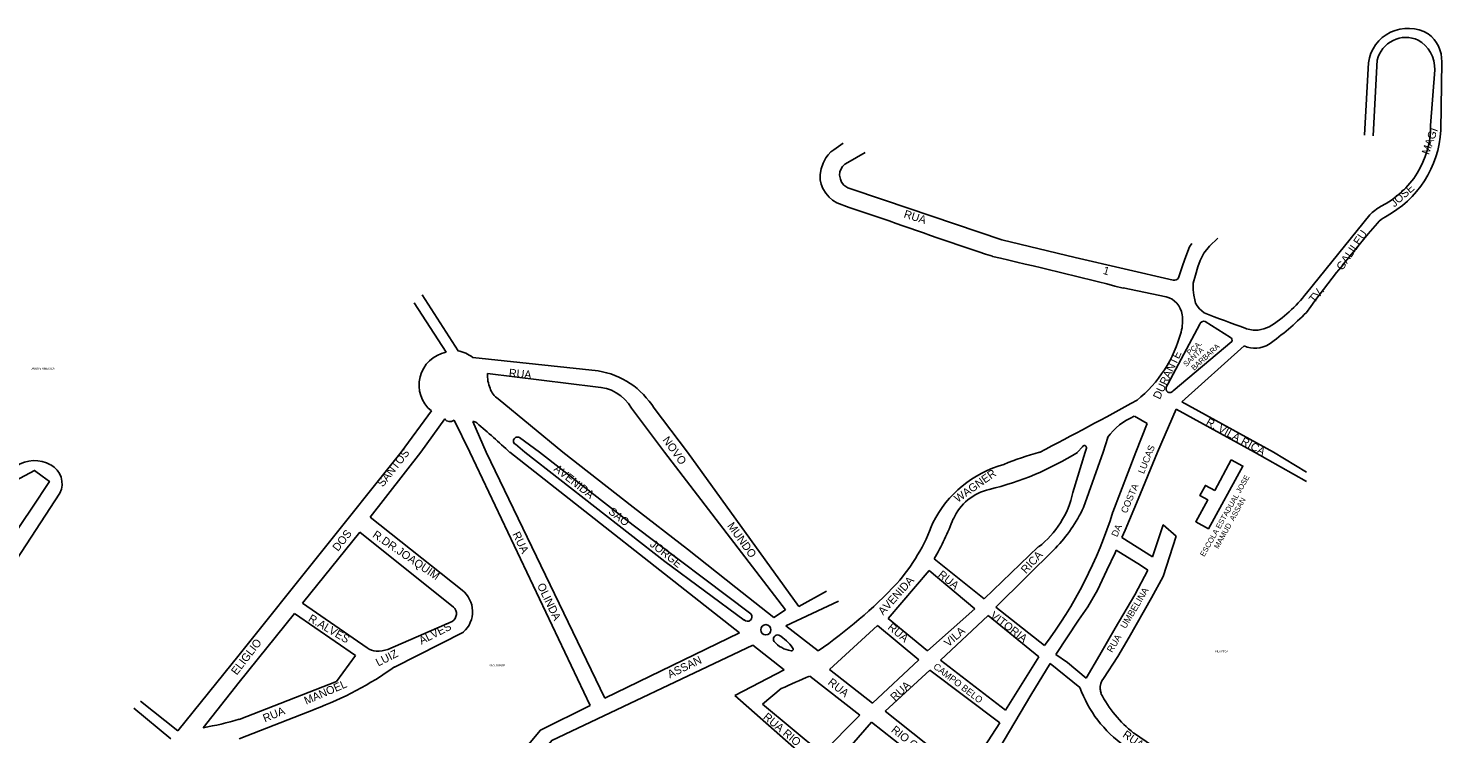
# Model space of a CAD drawing. Extents: x 325709 to 364434, y 7573432 to 7597073.
# Drawn here: x 335123 to 336183, y 7590791 to 7591320 of the extents above; entities that cross this region are included whole.
import ezdxf

# ---------------------------------------------------------------- set-up
doc = ezdxf.new("R2010")
doc.units = 0
for name, color, linetype in [('EDIFEXISTENT', 7, 'Continuous'), ('EDIFIDENTIF', 7, 'Continuous'), ('EDIFOBRAEXIS', 7, 'Continuous'), ('LIMITE_BAIRROS_MUNICIPIOS', 7, 'Continuous'), ('LOGRADOURO', 7, 'Continuous'), ('LOGRADOURO_TEXTO', 7, 'Continuous')]:
    doc.layers.add(name, color=color, linetype=linetype)

msp = doc.modelspace()

# ---------------------------------------------------------------- linework, layer by layer
at = {"layer": 'EDIFEXISTENT'}
msp.add_line((336012.7, 7590973.3), (336025, 7590996.4), dxfattribs=at)
msp.add_lwpolyline([(336025, 7590996.4), (336033.8, 7590991.6), (336007.9, 7590944.6), (335998.4, 7590949.9), (336007.4, 7590966.3), (336001.5, 7590969.5), (336005.7, 7590977.1), (336012.7, 7590973.3)], dxfattribs=at)
at = {"layer": 'EDIFOBRAEXIS'}
for p, q in [((335491.4, 7591012.9), (335506.4, 7591001.9)), ((335495.4, 7591001.9), (335488.4, 7591007.9))]:
    msp.add_line(p, q, dxfattribs=at)
for points in [[(335659.9, 7590876.3), (335600.5, 7590920.1), (335495.4, 7591001.9)], [(335506.4, 7591001.9), (335576.7, 7590947.3), (335664.9, 7590880.9)]]:
    msp.add_lwpolyline(points, dxfattribs=at)
msp.add_circle((335676.1, 7590869), 3.83, dxfattribs=at)
for centre, radius, start, end in [((335489.9, 7591010.4), 2.92, 59.0362, 239.0362), ((335662.3, 7590878.7), 3.39, 224.4723, 39.9732), ((335684.9, 7590862), 3.1, 73.1087, 215.8277), ((335670.3, 7590837.8), 31.3, 34.1923, 60.3582), ((335698.2, 7590874.1), 21.1, 221.1894, 261.4386), ((335695.4, 7590854.4), 1.23, 255.2992, 51.7204)]:
    msp.add_arc(centre, radius, start, end, dxfattribs=at)
at = {"layer": 'LOGRADOURO'}
for p, q in [((336127.8, 7591293.8), (336124.9, 7591239.5)), ((336134.5, 7591295.8), (336131.5, 7591238.9)), ((336174.4, 7591246.6), (336177.6, 7591288.4)), ((336182.2, 7591243.1), (336182.8, 7591294.3)), ((336081.4, 7591121.2), (336128.8, 7591179.9)), ((335418.4, 7591119.9), (335445.4, 7591077.9)), ((335944, 7591125), (335976.2, 7591118.3)), ((335412.4, 7591113.9), (335436.4, 7591076.9)), ((335977.4, 7591052.9), (336001.4, 7591097.9)), ((335988.1, 7591105), (335988.1, 7591105)), ((336005.4, 7591099.9), (336024.4, 7591087.9)), ((336025.4, 7591084.9), (335981.4, 7591047.9)), ((335987.9, 7591039.6), (336034.7, 7591081.6)), ((335456.4, 7591072.9), (335550.4, 7591062.9)), ((335467.4, 7591060.9), (335548.4, 7591050.9)), ((335425.4, 7591032.9), (335402.8, 7591001.9)), ((335524, 7591001.9), (335475.4, 7591041.9)), ((335575.4, 7591034.9), (335600.2, 7591001.9)), ((335592.4, 7591034.9), (335617.4, 7591001.9)), ((335969.7, 7591001.9), (335983.8, 7591034.2)), ((335983.8, 7591034.2), (336042.4, 7591001.9)), ((336056.6, 7591001.9), (335987.9, 7591039.6)), ((335417.4, 7591001.9), (335435.4, 7591026.9)), ((335442.4, 7591025.9), (335454.2, 7591001.9)), ((335466.5, 7591001.9), (335456.4, 7591024.9)), ((335952.4, 7591028.9), (335962, 7591023.4)), ((335962, 7591023.4), (335953.4, 7591001.9)), ((335928.9, 7591001.9), (335932.4, 7591012.9)), ((335281.4, 7590850.1), (335402.8, 7591001.9)), ((335379.6, 7590953.3), (335417.4, 7591001.9)), ((335454.2, 7591001.9), (335544.5, 7590812.2)), ((335555.4, 7590817.8), (335466.5, 7591001.9)), ((335484.2, 7591001.9), (335656.5, 7590866.7)), ((335600.2, 7591001.9), (335690.8, 7590884)), ((335700.8, 7590886.5), (335617.4, 7591001.9)), ((335915.6, 7591001.9), (335906.2, 7590971.9)), ((335909.8, 7591001.9), (335913.4, 7591005.9)), ((335914.2, 7590960.6), (335928.9, 7591001.9)), ((335916.4, 7591004.9), (335915.6, 7591001.9)), ((335953.4, 7591001.9), (335936.3, 7590957.2)), ((336042.4, 7591001.9), (336081.4, 7590980)), ((336056.6, 7591001.9), (336081.4, 7590987.1)), ((335843.6, 7590974.2), (335843.6, 7590974.2)), ((335448.5, 7590898.6), (335379.6, 7590953.3)), ((335328.8, 7590888.8), (335371.7, 7590942.2)), ((335371.7, 7590942.2), (335441.9, 7590886)), ((335966, 7590923.7), (335942.9, 7590938)), ((335880.4, 7590931.1), (335839.9, 7590892.1)), ((335848.6, 7590886), (335893.3, 7590930.1)), ((335839.9, 7590892.1), (335802.3, 7590922)), ((335767.8, 7590877.4), (335798.6, 7590913.5)), ((335798.6, 7590913.5), (335832.9, 7590884.6)), ((335721.7, 7590897.9), (335700.8, 7590886.5)), ((335377.2, 7590855.5), (335328.8, 7590888.8)), ((335730.5, 7590890.4), (335691.2, 7590871.9)), ((335832.9, 7590884.6), (335797.2, 7590853.2)), ((335885.1, 7590857.2), (335848.6, 7590886)), ((335322.9, 7590881.2), (335281.4, 7590829.7)), ((335368.6, 7590849.6), (335322.9, 7590881.2)), ((335441, 7590875.3), (335392.7, 7590854.3)), ((335690.8, 7590884), (335682.2, 7590878.2)), ((335797.2, 7590853.2), (335767.8, 7590877.4)), ((335807, 7590846.2), (335842.9, 7590879.6)), ((335842.9, 7590879.6), (335880.8, 7590848.8)), ((335397.9, 7590841.1), (335449.4, 7590867.3)), ((335656.5, 7590866.7), (335555.4, 7590817.8)), ((335691.2, 7590871.9), (335715.4, 7590853.1)), ((335723.9, 7590839.3), (335759.9, 7590872.2)), ((335759.9, 7590872.2), (335790.8, 7590846.5)), ((335666.3, 7590857.5), (335690, 7590839.1)), ((335235.4, 7590793.4), (335281.4, 7590850.1)), ((335790.8, 7590846.5), (335756, 7590813.9)), ((335855.9, 7590808.8), (335807, 7590846.2)), ((335880.8, 7590848.8), (335855.9, 7590808.8)), ((335889.2, 7590843.6), (335911.4, 7590825.8)), ((335690, 7590839.1), (335652.9, 7590819.7)), ((335709, 7590834.3), (335746.6, 7590804.9)), ((335756, 7590813.9), (335723.9, 7590839.3)), ((335765.7, 7590807.9), (335799.1, 7590838.8)), ((335799.1, 7590838.8), (335851.5, 7590799.3)), ((335281.4, 7590829.7), (335254.3, 7590795.6)), ((335673.7, 7590813.2), (335687.7, 7590824.9)), ((335230.1, 7590787.2), (335202.4, 7590810.3)), ((335207.4, 7590815.5), (335235.4, 7590793.4)), ((335652.9, 7590819.7), (335701.3, 7590777)), ((335718, 7590776.2), (335673.7, 7590813.2)), ((335281.4, 7590787.2), (335338.2, 7590809.6)), ((335746.6, 7590804.9), (335718, 7590776.2)), ((335723, 7590762.7), (335755.4, 7590799.7)), ((335755.4, 7590799.7), (335820.2, 7590748.9)), ((335826.1, 7590760.2), (335765.7, 7590807.9)), ((335851.5, 7590799.3), (335826.1, 7590760.2))]:
    msp.add_line(p, q, dxfattribs=at)
for points in [[(335734.1, 7591233.5), (335727.2, 7591228.6), (335724.8, 7591226.9), (335722.8, 7591224.8), (335721.1, 7591222.5), (335719.1, 7591218.6), (335717.5, 7591214.3), (335716.8, 7591210.1), (335716.9, 7591206.1), (335717.5, 7591202.8), (335718.8, 7591199.5), (335721, 7591196), (335723.5, 7591193), (335726.1, 7591190.7), (335729.4, 7591188.8), (335738.6, 7591185.3), (335763.4, 7591177)], [(335984.1, 7591131.3), (335983.6, 7591131), (335982.7, 7591130.8), (335981.5, 7591130.9), (335908.1, 7591147.9), (335853.1, 7591161.1), (335765.2, 7591190.8), (335737.5, 7591200.1), (335734.7, 7591202.1), (335732.9, 7591204.2), (335732, 7591206.6), (335731.4, 7591209.5), (335731.5, 7591212), (335732.5, 7591214.2), (335733.5, 7591216), (335735.4, 7591217.8), (335737.5, 7591219.1), (335750.6, 7591226.6)], [(336014.9, 7591162.4), (336008.7, 7591156.4), (336004.4, 7591151.2), (336001.7, 7591145.6), (335999.9, 7591140.8), (335998.1, 7591134.5), (335996.4, 7591128.7), (335996.4, 7591123.7), (335997, 7591119.6), (335997.7, 7591116.1), (335998.3, 7591113.6), (335999.4, 7591111.6), (336001.3, 7591109.5), (336004.6, 7591106.3)], [(335995.4, 7591158.3), (335993.7, 7591155.9), (335990.3, 7591146.7), (335988.2, 7591140.8), (335985.4, 7591132.6), (335984.6, 7591131.6), (335984.1, 7591131.3)], [(335682.2, 7590878.2), (335653.7, 7590900.6), (335617.5, 7590929.3), (335576.7, 7590960.8), (335524, 7591001.9)], [(335969.7, 7591001.9), (335955.3, 7590966.8), (335945.4, 7590943.7), (335942.9, 7590938)], [(335044.9, 7590944), (335127.8, 7590988.3), (335133.7, 7590984)], [(335133.7, 7590984), (335139.1, 7590980.1), (335125.8, 7590960.2), (335104.2, 7590927.9), (335094.3, 7590913.2)], [(335146.8, 7590971.4), (335070.9, 7590855.3), (334971.1, 7590705.6)], [(335929.2, 7590832.6), (335940.1, 7590848.9), (335948.6, 7590863.4), (335965.3, 7590892.9), (335974, 7590908.9), (335983.7, 7590939.1)], [(335983.7, 7590939.1), (335974.1, 7590947.5), (335966, 7590923.7)], [(335938.8, 7590928.6), (335937.9, 7590926.6), (335931.8, 7590913.7), (335924.8, 7590898.7), (335917.4, 7590886.2), (335910.6, 7590876.3), (335893.6, 7590850.4)], [(335938.8, 7590928.6), (335957, 7590917.5), (335962.5, 7590913.7)], [(335962.5, 7590913.7), (335952.8, 7590895.2), (335938, 7590870.1), (335926.6, 7590850.1), (335916.3, 7590832.8)], [(335492.7, 7590758.1), (335515.6, 7590786.1), (335666.3, 7590857.5)], [(335281.4, 7590801.9), (335354.3, 7590830.3), (335368.6, 7590849.6)], [(335834.2, 7590751.4), (335854.7, 7590786.3), (335874.9, 7590820.1), (335889.2, 7590843.6)], [(335916.3, 7590832.8), (335902.2, 7590844.5), (335893.6, 7590850.4)], [(335482.9, 7590764.8), (335507.1, 7590793.8), (335544.5, 7590812.2)], [(336015.1, 7590739.1), (335998.1, 7590760.3), (335965.9, 7590782.1), (335951.8, 7590791.7)]]:
    msp.add_lwpolyline(points, dxfattribs=at)
for centre, radius, start, end in [((336157.4, 7591289.6), 29.9, 59.2949, 171.9773), ((336156, 7591290.6), 22.1, 65.7536, 166.4741), ((336153.1, 7591289.3), 24.5, 357.7766, 60.8138), ((336157.8, 7591295.2), 25, 357.9461, 53.4616), ((336107.8, 7591246), 66.6, 295.9372, 0.5209), ((336103.7, 7591247.8), 78.6, 297.9919, 356.5663), ((336165.5, 7591140.6), 53.7, 122.1235, 133.0365), ((337149.4, 7595085.9), 4147.3, 250.4768, 251.6834), ((336919.1, 7590494.6), 1037.5, 139.1218, 143.8441), ((336153.8, 7591155.9), 26.1, 120.374, 137.2877), ((334819.7, 7586696.4), 4569, 75.7556, 77.0199), ((335972.4, 7591102.9), 15.9, 7.5137, 76.3181), ((335998.8, 7591184.5), 104.1, 301.6303, 322.5095), ((335932.7, 7591253.2), 208.7, 305.3156, 315.4171), ((335955, 7591100.3), 33.5, 345.5635, 8.0786), ((336004.4, 7591096.9), 3.16, 71.5865, 161.5436), ((336667.9, 7592851.4), 1866.9, 249.1883, 250.1965), ((335893, 7591116.8), 97.6, 308.9666, 345.2229), ((336023.4, 7591085.9), 2.24, 333.4349, 63.435), ((336043.8, 7591118.8), 25.4, 250.5827, 273.0836), ((336041, 7591123), 29.8, 278.0826, 294.585), ((335441.2, 7591052.3), 25, 100.9903, 230.9372), ((335439.6, 7591050.7), 27.9, 53.0287, 78.0833), ((336042.8, 7591100.1), 20.2, 246.2595, 301.5142), ((335495.9, 7591060.4), 28.5, 178.9949, 201.6148), ((335541.1, 7591003.5), 60.1, 31.4748, 81.1451), ((335484.4, 7591054.9), 15.8, 198.4349, 235.3048), ((335548.1, 7591019.6), 31.3, 29.2807, 89.4179), ((335982.5, 7591049.3), 6.29, 144.7851, 192.5951), ((335978.9, 7591050), 3.25, 219.6849, 320.3151), ((333954.1, 7594697.2), 4167.7, 297.5443, 298.6821), ((335439.4, 7591029.9), 5, 216.8699, 306.8699), ((335456.9, 7591021.4), 3.54, 45, 98.1301), ((335104.9, 7590599.7), 552.8, 46.6796, 50.1143), ((335969.1, 7590987.5), 44.7, 111.9963, 145.3233), ((335791.2, 7591191.9), 224, 283.5384, 301.9686), ((335928.4, 7590819.9), 188, 104.484, 113.1115), ((335914.9, 7591005.4), 1.58, 71.5651, 161.5651), ((335914.9, 7591005.4), 1.58, 341.5651, 71.5651), ((335127.8, 7590971.2), 24.5, 60.0678, 123.5626), ((335132.8, 7590978.4), 15.8, 333.4621, 62.6894), ((335876.6, 7590911.7), 84, 105.1917, 153.6054), ((335852.2, 7590936.2), 38.9, 102.6822, 155.8906), ((335838.8, 7590985.9), 68.9, 307.2158, 348.2264), ((335811.4, 7591008.7), 113.5, 316.1594, 334.918), ((335665.2, 7590999.2), 145.1, 318.7706, 339.7998), ((335633.9, 7591020.9), 195.2, 329.5647, 339.3722), ((335617.8, 7591057.3), 333.9, 323.185, 342.557), ((335436, 7590882.6), 20.3, 311.3721, 52.0528), ((335498.4, 7591166.6), 381.2, 304.6826, 316.3644), ((335437.6, 7590881), 6.62, 300.3248, 49.3896), ((335384.7, 7590864.8), 11.9, 231.0783, 267.4161), ((335384.7, 7590876.5), 23.6, 268.6819, 289.797), ((335243.7, 7591060.7), 268.3, 290.608, 305.0788), ((335912.5, 7590343.4), 531.4, 112.5221, 115.031), ((335939.2, 7590825.2), 12.4, 143.4391, 183.806), ((335999.4, 7590858.2), 93.7, 200.1991, 234.5451), ((335939.2, 7590825.2), 12.4, 183.806, 197.6007), ((336011.1, 7590865.6), 94.8, 207.8084, 231.2698), ((335212.2, 7591037.9), 245.9, 279.8625, 286.3352)]:
    msp.add_arc(centre, radius, start, end, dxfattribs=at)

# ---------------------------------------------------------------- texts
at = {"layer": 'EDIFIDENTIF'}
for s, rotation, p in [('ESCOLA ESTADUAL JOSE', 60.394, (336004.8, 7590923.4)), ('MAMUD  ASSAN', 60.9531, (336015.3, 7590929.3))]:
    msp.add_text(s, height=4, rotation=rotation, dxfattribs=at).set_placement(p)
at = {"layer": 'LIMITE_BAIRROS_MUNICIPIOS'}
for s, p in [('JARDIM AMERICA', (335125.3, 7591063.9)), ('VILA RICA', (336012.7, 7590852.1)), ('SAO JORGE', (335468.6, 7590841.5))]:
    msp.add_text(s, height=1.5, dxfattribs=at).set_placement(p)
at = {"layer": 'LOGRADOURO_TEXTO'}
for s, height, rotation, p in [('MAGI', 6, 70.4008, (336173.2, 7591224.4)), ('JOSE', 6, 41.6503, (336147.3, 7591185.2)), ('RUA', 6, 342.6184, (335779.1, 7591177.9)), ('GALILEU', 6, 55.9226, (336108.3, 7591137.7)), ('1', 6, 343.6142, (335928.4, 7591135.7)), ('TV.', 6, 50.2938, (336087.2, 7591113.3)), ('DURANTE', 6, 64.9554, (335971.5, 7591041.1)), ('SANTA', 4, 42.3957, (335991.2, 7591065.7)), ('PCA.', 4, 42.3957, (335993.9, 7591074.3)), ('BARBARA', 4, 42.3957, (335997.2, 7591062.9)), ('RUA', 6, 354.579, (335483.3, 7591058.6)), ('R. VILA RICA', 6, 331.2748, (336005.5, 7591022.8)), ('NOVO', 6, 305.8527, (335598.4, 7591011.1)), ('SANTOS', 6, 51.706, (335389, 7590975.5)), ('LUCAS', 5, 67.6315, (335959.5, 7590985.4)), ('AVENIDA', 6, 321.8886, (335516.7, 7590988.6)), ('WAGNER', 6, 35.2802, (335820, 7590964)), ('COSTA', 5, 66.8267, (335946.6, 7590955.8)), ('SAO', 6, 321.8886, (335557.6, 7590956.6)), ('MUNDO', 6, 305.8527, (335646.9, 7590946.8)), ('DOS', 6, 51.706, (335355.4, 7590927.3)), ('R.DR.JOAQUIM', 6, 325.7094, (335380.8, 7590938.8)), ('RUA', 6, 295.7738, (335486, 7590940.7)), ('DA', 5, 66.4406, (335939.5, 7590938.1)), ('JORGE', 6, 321.8886, (335588.7, 7590932.1)), ('RICA', 6, 47.2209, (335871.1, 7590910.6)), ('AVENIDA', 6, 47.9962, (335764.1, 7590879.5)), ('RUA', 6, 321.3563, (335804.7, 7590909.3)), ('OLINDA', 6, 295.7738, (335504.5, 7590902.2)), ('UMBELINA', 5, 59.1558, (335945.8, 7590869.4)), ('R.ALVES', 6, 329.5898, (335332.6, 7590875.8)), ('ALVES', 6, 26.9675, (335418, 7590857.8)), ('RUA', 6, 320.5251, (335767, 7590870)), ('VITORIA', 6, 322.5688, (335843.8, 7590878.6)), ('VILA', 6, 41.3199, (335813, 7590855.8)), ('RUA', 5, 59.0397, (335935.7, 7590851.5)), ('ELIGLIO', 6, 52.2888, (335279.5, 7590834.6)), ('LUIZ', 6, 26.9675, (335385.6, 7590841.4)), ('ASSAN', 6, 25.7943, (335604.2, 7590832.5)), ('CAMPO BELO', 5, 322.5183, (335801.2, 7590840.5)), ('RUA', 6, 321.6725, (335722.1, 7590828.6)), ('MANOEL', 6, 23.3649, (335331.6, 7590812.8)), ('RUA', 6, 43.085, (335772.9, 7590815.2)), ('RUA ', 6, 22.3216, (335300.6, 7590799.6)), ('RUA RIO', 6, 320.1691, (335673.6, 7590802.8)), ('RIO CLARO', 6, 321.678, (335769.6, 7590793)), ('RUA', 6, 325.7155, (335943, 7590789.1))]:
    msp.add_text(s, height=height, rotation=rotation, dxfattribs=at).set_placement(p)

doc.saveas('drawing.dxf')
